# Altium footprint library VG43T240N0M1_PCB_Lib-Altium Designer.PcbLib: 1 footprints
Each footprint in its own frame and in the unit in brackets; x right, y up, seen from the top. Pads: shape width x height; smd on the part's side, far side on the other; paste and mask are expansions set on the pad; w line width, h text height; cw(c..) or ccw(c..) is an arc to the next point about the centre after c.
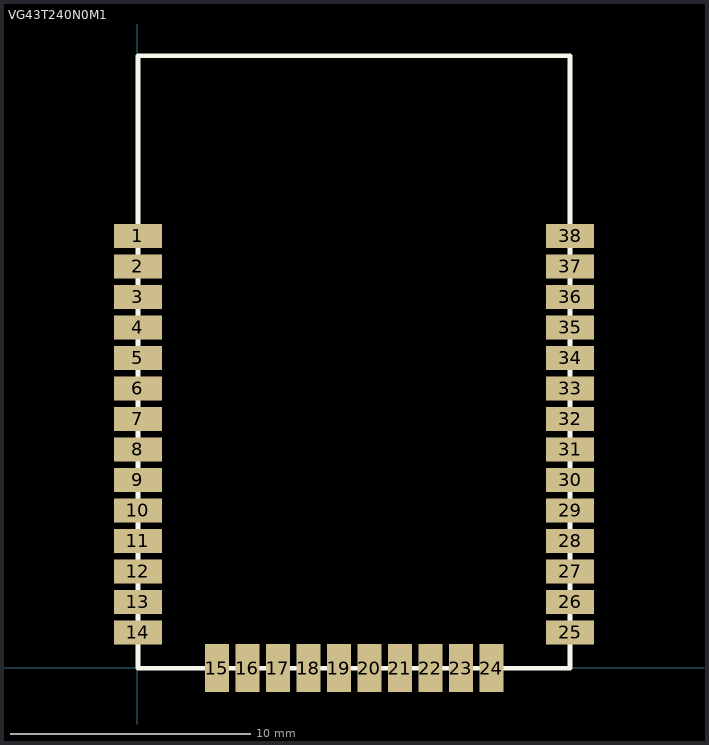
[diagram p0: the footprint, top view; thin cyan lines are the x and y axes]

## VG43T240N0M1 [mm]
pads (38):
  rect 2x1 smd: 1(0.034,17.984) 2(0.034,16.714) 3(0.034,15.444) 4(0.034,14.174) 5(0.034,12.904) 6(0.034,11.634) 7(0.034,10.364) 8(0.034,9.094) 9(0.034,7.824) 10(0.034,6.554) 11(0.034,5.284) 12(0.034,4.014) 13(0.034,2.744) 14(0.034,1.474) 25(18.034,1.474) 26(18.034,2.744) 27(18.034,4.014) 28(18.034,5.284) 29(18.034,6.554) 30(18.034,7.824) 31(18.034,9.094) 32(18.034,10.364) 33(18.034,11.634) 34(18.034,12.904) 35(18.034,14.174) 36(18.034,15.444) 37(18.034,16.714) 38(18.034,17.984)
  rect 1x2 smd: 15(3.324,-0.016) 16(4.594,-0.016) 17(5.864,-0.016) 18(7.134,-0.016) 19(8.404,-0.016) 20(9.674,-0.016) 21(10.944,-0.016) 22(12.214,-0.016) 23(13.484,-0.016) 24(14.754,-0.016)
Top Overlay:
  lines w0.2: 0.034,-0.016 0.034,25.484 18.034,25.484 18.034,-0.016 0.034,-0.016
